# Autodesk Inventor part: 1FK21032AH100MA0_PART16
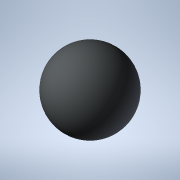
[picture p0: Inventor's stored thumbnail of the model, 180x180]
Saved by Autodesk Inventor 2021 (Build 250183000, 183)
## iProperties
Created: 2025-04
Part Number: 1FK21032AH100MA0_PART16
Material: Generic
Catalog Web Link: www.3dfindit.com
Description: -Servo synchronous motor
Document SubType Name: Modeling
Designer: psAdmin
Mass: 0.113097 g
Surface Area: 1.13097 cm^2
Volume: 0.113097 cm^3
Density: 1 g/cm^3
Appearance: PSOLRGB-212-217-219
Category: PARTsolutions
Title: 1FK21032AH100MA0_PART16
Author: Cadenas PARTsolutions
Comments: Servo synchronous motor
Sending System: PARTsolutions
Preprocessor: ST-DEVELOPER v19.3
PSOL_IDENT_0: {$CADENAS_DATA/23d-libs/siemens_ag/_cat_/12/33/1fk21032ah100ma0.prj},216 {VTYP=3D},{NB=1FK21032AH100
PSOL_IDENT_1: MA0_PART16},{LINA=1FK21032AH100MA0_PART16},{NN=1FK21032AH100MA0_PART16},{NOPRJ=TRUE},{DATE=19.08.202
PSOL_IDENT_2: 5 14:00:27},{GEOMDATE=30.07.2025 02:02:58},{VERSION=},{LINEID=10},{WBVAR=},{WBNUMERIC=}  {NB=1FK2103
PSOL_IDENT_3: 2AH100MA0_PART16},{LINA=1FK21032AH100MA0_PART16},{KT=DUMMY},{PREVIEW=../../../_pool_/d3/78/p_d211_xx
PSOL_IDENT_4: _00934j.png},{DESCSHORT=SIMOTICS S-1FK2 HD, SINAMICS S210 3AC 400V-480V, 0.59 Nm, 4500 rpm},{DESCLON
PSOL_IDENT_5: G=SIMOTICS S-1FK2 HD servo motor M0=0.64 Nm; PN = 0.28 kW at nN=4500 rpm (380-480 V); PN = 0.167 kW
PSOL_IDENT_6: at nN=2500 rpm (200-240 V); with holding brake; degree of protection IP64; cylindrical shaft D14 x 3
PSOL_IDENT_7: 0 mm; absolute encoder 22-bit + 12-bit multiturn (encoder AM22DQC); with OCC interface; plug size M1
PSOL_IDENT_8: 7, rotatable; SIMOTICS S-1FK2 servomotorfor a wide range of uses in industrial environments. SIMOTIC
PSOL_IDENT_9: S S‑1FK2 servomotors are compact synchronous motors with a high dynamic performance that set themsel
PSOL_IDENT_10: ves apart as a result of their high power density, degree of protection and overload capability. The
PSOL_IDENT_11: motors are available in two variants: as High Dynamic variant (highest dynamic performance as a res
PSOL_IDENT_12: ult of the low intrinsic moment of inertia for applications demanding a high dynamic performance wit
PSOL_IDENT_13: h low moved masses) - and as Compact variant (precise and stable closed-loop control for medium up t
PSOL_IDENT_14: o large moved masses as a result of a medium intrinsic moment of inertia). SIMOTICSS‑1FK2 servomotor
PSOL_IDENT_15: s fully exploit their strengths in a system with the SINAMICSS210 frequency converter and simple con
PSOL_IDENT_16: nection using the one cable connection (OCC). Advantages include the short control and positioning t
PSOL_IDENT_17: imes, fast and precise correction of disturbing quantities as well as stable control with a high dyn
PSOL_IDENT_18: amic performance. The servo motors can be configured to address a wide range of requirements. For ex
PSOL_IDENT_19: ample with and without holding brake, IP64 or IP65 degree of protection, singleturn or multiturn abs
PSOL_IDENT_20: olute encoders - to name just a few. Further, the servomotors are available in different shaft heigh
PSOL_IDENT_21: ts extending from 20 to 100. A shaft sealing ring is available to achieve an IP65 degree of protecti
PSOL_IDENT_22: on and for subsequent mounting at the motor or as spare part. SIMOTICS - the optimum motor for each
PSOL_IDENT_23: and every motion control application.},{INTNO=195125315563},{SUPPLIERALTNO=1FK2103-2AH10-0MA0},{MANU
PSOL_IDENT_24: ID=1FK21032AH100MA0},{MANUNAME=Siemens},{MANUTYPEDESC=SYNCHRONOUS MOTOR 1FK2 HD 0,64 NM},{AAU732=SIM
PSOL_IDENT_25: OTICS},{AAO057=S-1FK2},{AAU734=SIMOTICS S-1FK2 HD servo motor M0=0.64 Nm; PN = 0.28 kW at nN=4500 rp
PSOL_IDENT_26: m (380-480 V); PN = 0.167 kW at nN=2500 rpm (200-240 V); with holding brake; degree of protection IP
PSOL_IDENT_27: 64; cylindrical shaft D14 x 30 mm; absolute encoder 22-bit + 12-bit multiturn (encoder AM22DQC); wit
PSOL_IDENT_28: h OCC interface; plug size M17, rotatable;},{AAW338=SYNCHRONOUS MOTOR 1FK2 HD 0,64 NM},{AAO742=SIMOT
PSOL_IDENT_29: ICS},{AAO663=4034106444723},{NOCUPEROU=1},{PRICEQUANTITY=1},{QUANTITYMIN=1},{QUANTITYINT=1},{CTN=850
PSOL_IDENT_30: 15100},{COO=RO},{AAO676=1FK2103-2AH10-0MA0},{AAO677=Siemens AG},{ORDERUNIT=C62},{CONTENTUNIT=C62}
NB: 1FK21032AH100MA0_PART16
NT: Servo synchronous motor
NBSYN: $MANUID._PART16
LINA: 1FK21032AH100MA0_PART16
CATALOG: SIEMENS
PREVIEW: ../../../_pool_/d3/78/p_d211_xx_00934j.png
DESCSHORT: SIMOTICS S-1FK2 HD, SINAMICS S210 3AC 400V-480V, 0.59 Nm, 4500 rpm
DESCLONG: SIMOTICS S-1FK2 HD servo motor M0=0.64 Nm; PN = 0.28 kW at nN=4500 rpm (380-480 V); PN = 0.167 kW at nN=2500 rpm (200-240 V); with holding brake; degree of prot
INTNO: 195125315563
SUPPLIERALTNO: 1FK2103-2AH10-0MA0
MANUID: 1FK21032AH100MA0
MANUNAME: Siemens
MANUTYPEDESC: SYNCHRONOUS MOTOR 1FK2 HD 0,64 NM
AAU732: SIMOTICS
AAO057: S-1FK2
AAU734: SIMOTICS S-1FK2 HD servo motor M0=0.64 Nm; PN = 0.28 kW at nN=4500 rpm (380-480 V); PN = 0.167 kW at nN=2500 rpm (200-240 V); with holding brake; degree of prot
AAW338: SYNCHRONOUS MOTOR 1FK2 HD 0,64 NM
AAO742: SIMOTICS
AAO663: 4034106444723.0
NOCUPEROU: 1
PRICEQUANTITY: 1
QUANTITYMIN: 1
QUANTITYINT: 1
CTN: 85015100
COO: RO
ARTICLENO: 1FK21032AH100MA0_PART16
BOMINFO: 1FK21032AH100MA0_PART16
CREATOR: CADENAS GmbH
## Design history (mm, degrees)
feature "2025_04_17_15_06_16_0705"
body "Solid1"
